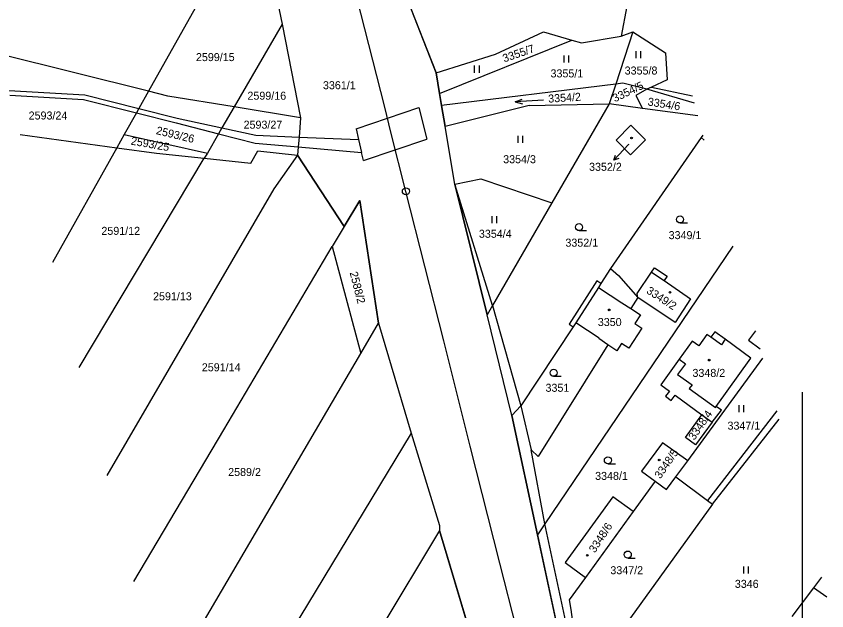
# Model space of a CAD drawing. Extents: x -754710 to -754206, y -1169123 to -1168234.
# Drawn here: x -754541.8 to -754369.7, y -1168754.2 to -1168628 of the extents above; entities that cross this region are included whole.
import ezdxf

# ---------------------------------------------------------------- set-up
doc = ezdxf.new("R2010")
doc.units = 0
for name, color, linetype in [('Vrstva 1', 7, 'Continuous'), ('Vrstva 16', 7, 'Continuous'), ('Vrstva 18', 7, 'Continuous'), ('Vrstva 19', 7, 'Continuous'), ('Vrstva 25', 7, 'Continuous'), ('Vrstva 3', 7, 'Continuous'), ('Vrstva 4', 7, 'Continuous'), ('Vrstva 6', 7, 'Continuous')]:
    doc.layers.add(name, color=color, linetype=linetype)

msp = doc.modelspace()

# ---------------------------------------------------------------- linework, layer by layer
at = {"layer": 'Vrstva 1'}
for p, q in [((-754463.59, -1168647.3), (-754471.68, -1168615.35)), ((-754460.6, -1168619.67), (-754452.67, -1168639.96)), ((-754486.32, -1168624.94), (-754485.38, -1168629.68)), ((-754412.19, -1168625.83), (-754413.36, -1168632.2)), ((-754485.38, -1168629.68), (-754481.43, -1168649.55)), ((-754440.06, -1168636.05), (-754429.88, -1168631.27)), ((-754429.88, -1168631.27), (-754423.86, -1168633.01)), ((-754421.81, -1168633.6), (-754413.36, -1168632.2)), ((-754413.36, -1168632.2), (-754410.89, -1168631.27)), ((-754410.89, -1168631.27), (-754404, -1168635.7)), ((-754423.86, -1168633.01), (-754421.81, -1168633.6)), ((-754513.7, -1168643.9), (-754545.33, -1168636.05)), ((-754452.67, -1168639.96), (-754440.06, -1168636.05)), ((-754404, -1168635.7), (-754403.6, -1168641.5)), ((-754452.67, -1168639.96), (-754451.93, -1168644.34)), ((-754414.55, -1168642.38), (-754451.5, -1168646.92)), ((-754413.07, -1168642.2), (-754414.55, -1168642.38)), ((-754407.94, -1168643.48), (-754413.07, -1168642.2)), ((-754406.98, -1168643.04), (-754407.94, -1168643.48)), ((-754403.6, -1168641.5), (-754406.98, -1168643.04)), ((-754406.98, -1168643.04), (-754398.28, -1168644.85)), ((-754509.58, -1168644.92), (-754513.7, -1168643.9)), ((-754495.56, -1168647.23), (-754509.58, -1168644.92)), ((-754451.93, -1168644.34), (-754451.5, -1168646.92)), ((-754432.9, -1168646.9), (-754415.92, -1168646.53)), ((-754415.92, -1168646.53), (-754428.1, -1168667.57)), ((-754408.83, -1168647.52), (-754415.92, -1168646.53)), ((-754481.43, -1168649.55), (-754495.56, -1168647.23)), ((-754462.25, -1168652.61), (-754463.59, -1168647.3)), ((-754451.5, -1168646.92), (-754450.74, -1168651.41)), ((-754432.9, -1168646.9), (-754450.74, -1168651.41)), ((-754397.13, -1168649.14), (-754408.83, -1168647.52)), ((-754481.43, -1168649.55), (-754481.76, -1168653.61)), ((-754448.68, -1168663.63), (-754450.74, -1168651.41)), ((-754411.33, -1168651.11), (-754414.47, -1168654.27)), ((-754408.23, -1168654.21), (-754411.33, -1168651.11)), ((-754540.99, -1168653.08), (-754520.42, -1168655.89)), ((-754459.07, -1168665.21), (-754462.25, -1168652.61)), ((-754396.05, -1168653.18), (-754396.4, -1168653.69)), ((-754481.76, -1168653.61), (-754481.94, -1168655.69)), ((-754396.4, -1168653.69), (-754415.64, -1168681.53)), ((-754414.47, -1168654.27), (-754411.38, -1168657.36)), ((-754411.38, -1168657.36), (-754408.23, -1168654.21)), ((-754396.4, -1168653.69), (-754395.75, -1168654.27)), ((-754520.42, -1168655.89), (-754512.05, -1168657.04)), ((-754492.02, -1168659.16), (-754490.52, -1168656.57)), ((-754490.52, -1168656.57), (-754482.08, -1168657.45)), ((-754481.94, -1168655.69), (-754482.08, -1168657.45)), ((-754512.05, -1168657.04), (-754501.88, -1168658.12)), ((-754501.88, -1168658.12), (-754492.02, -1168659.16)), ((-754472.22, -1168672.58), (-754482.08, -1168657.45)), ((-754448.68, -1168663.63), (-754441.87, -1168691.36)), ((-754451.06, -1168696.87), (-754459.07, -1168665.21)), ((-754468.86, -1168667.12), (-754472.22, -1168672.58)), ((-754464.89, -1168693.12), (-754468.86, -1168667.12)), ((-754428.1, -1168667.57), (-754440.72, -1168689.36)), ((-754472.22, -1168672.58), (-754474.73, -1168676.83)), ((-754497.71, -1168715.77), (-754474.73, -1168676.83)), ((-754474.73, -1168676.83), (-754468.68, -1168699.59)), ((-754389.72, -1168676.8), (-754429.57, -1168735.76)), ((-754415.64, -1168681.53), (-754417.68, -1168684.71)), ((-754415.64, -1168681.53), (-754413.94, -1168682.99)), ((-754410.01, -1168686.86), (-754406.97, -1168682.3)), ((-754406.97, -1168682.3), (-754406.35, -1168681.37)), ((-754406.35, -1168681.37), (-754403.66, -1168683.16)), ((-754418.53, -1168684.17), (-754424.41, -1168693.34)), ((-754417.68, -1168684.71), (-754418.53, -1168684.17)), ((-754413.94, -1168682.99), (-754409.88, -1168687.67)), ((-754403.66, -1168683.16), (-754404.29, -1168684.1)), ((-754404.29, -1168684.1), (-754398.67, -1168687.96)), ((-754409.88, -1168687.67), (-754411.36, -1168690.04)), ((-754409.88, -1168687.67), (-754410.01, -1168686.86)), ((-754401.94, -1168693.01), (-754409.88, -1168687.67)), ((-754440.72, -1168689.36), (-754441.87, -1168691.36)), ((-754398.67, -1168687.96), (-754401.94, -1168693.01)), ((-754436.63, -1168712.73), (-754441.87, -1168691.36)), ((-754411.36, -1168690.04), (-754409.3, -1168691.38)), ((-754409.3, -1168691.38), (-754410.48, -1168693.2)), ((-754423.03, -1168693.04), (-754423.57, -1168693.88)), ((-754418.08, -1168696.32), (-754423.03, -1168693.04)), ((-754468.68, -1168699.59), (-754464.89, -1168693.12)), ((-754464.89, -1168693.12), (-754457.95, -1168716.5)), ((-754423.57, -1168693.88), (-754434.7, -1168710.71)), ((-754424.41, -1168693.34), (-754423.57, -1168693.88)), ((-754408.98, -1168694.18), (-754411.76, -1168698.45)), ((-754410.48, -1168693.2), (-754408.98, -1168694.18)), ((-754384.9, -1168694.76), (-754386.35, -1168696.77)), ((-754418.1, -1168696.41), (-754418.08, -1168696.32)), ((-754416.19, -1168697.75), (-754418.1, -1168696.41)), ((-754395.18, -1168695.53), (-754396.93, -1168697.95)), ((-754394.33, -1168696.13), (-754395.18, -1168695.53)), ((-754393.52, -1168694.99), (-754394.33, -1168696.13)), ((-754391.34, -1168696.54), (-754393.52, -1168694.99)), ((-754385.86, -1168700.53), (-754391.34, -1168696.54)), ((-754445.42, -1168719.24), (-754451.06, -1168696.87)), ((-754416.19, -1168697.75), (-754431.01, -1168721.45)), ((-754414.34, -1168699.04), (-754416.19, -1168697.75)), ((-754413.3, -1168697.45), (-754414.34, -1168699.04)), ((-754411.76, -1168698.45), (-754413.3, -1168697.45)), ((-754398.33, -1168696.96), (-754401.06, -1168700.75)), ((-754396.93, -1168697.95), (-754398.33, -1168696.96)), ((-754386.35, -1168696.77), (-754383.88, -1168698.57)), ((-754510.83, -1168771.56), (-754468.68, -1168699.59)), ((-754401.06, -1168700.75), (-754404.95, -1168706.25)), ((-754399.26, -1168722.38), (-754383.35, -1168700.57)), ((-754393.21, -1168710.84), (-754385.86, -1168700.53)), ((-754404.95, -1168706.25), (-754403.16, -1168707.56)), ((-754403.16, -1168707.56), (-754403.96, -1168708.65)), ((-754402.75, -1168709.54), (-754401.95, -1168708.44)), ((-754401.95, -1168708.44), (-754396.29, -1168712.57)), ((-754403.96, -1168708.65), (-754402.75, -1168709.54)), ((-754434.7, -1168710.71), (-754436.63, -1168712.73)), ((-754434.7, -1168710.71), (-754432.51, -1168719.99)), ((-754380.36, -1168711.71), (-754395.05, -1168730.8)), ((-754394.09, -1168714.17), (-754392.08, -1168711.61)), ((-754392.08, -1168711.61), (-754393.21, -1168710.84)), ((-754436.63, -1168712.73), (-754431.15, -1168738.1)), ((-754399.77, -1168717.39), (-754396.29, -1168712.57)), ((-754396.29, -1168712.57), (-754394.09, -1168714.17)), ((-754394.09, -1168714.17), (-754397.64, -1168718.98)), ((-754516.83, -1168748.01), (-754497.71, -1168715.77)), ((-754457.95, -1168716.5), (-754505.08, -1168794.17)), ((-754457.95, -1168716.5), (-754451.94, -1168736.1)), ((-754404.62, -1168718.51), (-754409.11, -1168724.52)), ((-754399.26, -1168722.38), (-754404.62, -1168718.51)), ((-754397.64, -1168718.98), (-754399.77, -1168717.39)), ((-754439.13, -1168744.08), (-754445.42, -1168719.24)), ((-754431.01, -1168721.45), (-754432.51, -1168719.99)), ((-754401.8, -1168725.79), (-754399.26, -1168722.38)), ((-754409.11, -1168724.52), (-754406.17, -1168726.67)), ((-754403.75, -1168728.44), (-754401.8, -1168725.79)), ((-754401.8, -1168725.79), (-754395.05, -1168730.8)), ((-754406.17, -1168726.67), (-754410.83, -1168733.1)), ((-754406.17, -1168726.67), (-754403.75, -1168728.44)), ((-754415.14, -1168729.97), (-754425.29, -1168743.98)), ((-754410.83, -1168733.1), (-754415.14, -1168729.97)), ((-754395.05, -1168730.8), (-754394.02, -1168731.56)), ((-754394.02, -1168731.56), (-754421.18, -1168769.2)), ((-754410.83, -1168733.1), (-754420.98, -1168747.1)), ((-754451.94, -1168736.1), (-754451.95, -1168737.18)), ((-754451.95, -1168737.18), (-754499.53, -1168815.95)), ((-754445.36, -1168759.13), (-754451.95, -1168737.18)), ((-754431.15, -1168738.1), (-754426.48, -1168759.73)), ((-754434.25, -1168763.41), (-754439.13, -1168744.08)), ((-754425.29, -1168743.98), (-754420.98, -1168747.1)), ((-754420.98, -1168747.1), (-754424.45, -1168751.89)), ((-754370.88, -1168747.09), (-754372.58, -1168749.34)), ((-754372.58, -1168749.34), (-754377.16, -1168755.42)), ((-754369.75, -1168751.32), (-754372.58, -1168749.34)), ((-754424.45, -1168751.89), (-754424.07, -1168753.9)), ((-754424.07, -1168753.9), (-754423.79, -1168756.05))]:
    msp.add_line(p, q, dxfattribs=at)
for points in [[(-754378.16, -1168960.13), (-754379.05, -1168945.33), (-754396.56, -1168868.29), (-754401.41, -1168844.82), (-754410.22, -1168837.85), (-754411.61, -1168830.11), (-754417.05, -1168810.66), (-754423.83, -1168771.88), (-754425.2, -1168765.6), (-754426.48, -1168759.73), (-754431.15, -1168738.1), (-754436.63, -1168712.73), (-754441.87, -1168691.36), (-754448.68, -1168663.63), (-754450.74, -1168651.41), (-754451.5, -1168646.92), (-754451.93, -1168644.34), (-754452.67, -1168639.96), (-754460.6, -1168619.67)], [(-754486.32, -1168624.94), (-754485.38, -1168629.68), (-754481.43, -1168649.55), (-754481.76, -1168653.61), (-754481.94, -1168655.69), (-754482.08, -1168657.45), (-754472.22, -1168672.58), (-754468.86, -1168667.12), (-754464.89, -1168693.12), (-754457.95, -1168716.5), (-754451.94, -1168736.1), (-754451.95, -1168737.18), (-754445.36, -1168759.13)]]:
    msp.add_lwpolyline(points, dxfattribs=at)
msp.add_circle((-754459.08, -1168665.13), 0.75, dxfattribs=at)
at = {"layer": 'Vrstva 16'}
for p in [(-754411.74, -1168655.16), (-754414.94, -1168658.54)]:
    msp.add_line(p, (-754412.88, -1168656.36), dxfattribs=at)
msp.add_lwpolyline([(-754413.89, -1168658.16), (-754414.94, -1168658.54), (-754414.62, -1168657.47)], dxfattribs=at)
at = {"layer": 'Vrstva 25'}
for p, q in [((-754425.48, -1168637.81), (-754425.48, -1168636.31)), ((-754424.48, -1168637.81), (-754424.48, -1168636.31)), ((-754410.2, -1168636.9), (-754410.2, -1168635.4)), ((-754409.2, -1168636.9), (-754409.2, -1168635.4)), ((-754444.49, -1168639.95), (-754444.49, -1168638.45)), ((-754443.49, -1168639.95), (-754443.49, -1168638.45)), ((-754435.23, -1168654.85), (-754435.23, -1168653.35)), ((-754434.23, -1168654.85), (-754434.23, -1168653.35)), ((-754440.76, -1168671.92), (-754440.76, -1168670.42)), ((-754439.76, -1168671.92), (-754439.76, -1168670.42)), ((-754400.89, -1168671.86), (-754399.29, -1168671.86)), ((-754422.33, -1168673.49), (-754420.73, -1168673.49)), ((-754427.73, -1168704.41), (-754426.13, -1168704.41)), ((-754388.33, -1168712.05), (-754388.33, -1168710.55)), ((-754387.33, -1168712.05), (-754387.33, -1168710.55)), ((-754416.21, -1168722.99), (-754414.61, -1168722.99)), ((-754411.99, -1168743.01), (-754410.39, -1168743.01)), ((-754387.34, -1168746.31), (-754387.34, -1168744.81)), ((-754386.34, -1168746.31), (-754386.34, -1168744.81))]:
    msp.add_line(p, q, dxfattribs=at)
for points in [[(-754435.89, -1168646.14), (-754434.42, -1168645.55)], [(-754429.9, -1168645.8), (-754435.89, -1168646.14), (-754434.36, -1168646.55)]]:
    msp.add_lwpolyline(points, dxfattribs=at)
for centre, radius in [((-754411.19, -1168653.81), 0.175), ((-754400.89, -1168671.11), 0.75), ((-754422.33, -1168672.74), 0.75), ((-754403.03, -1168686.58), 0.175), ((-754415.93, -1168690.31), 0.175), ((-754394.71, -1168700.98), 0.175), ((-754427.73, -1168703.66), 0.75), ((-754416.21, -1168722.24), 0.75), ((-754405.31, -1168722.17), 0.175), ((-754420.59, -1168742.41), 0.175), ((-754411.99, -1168742.26), 0.75)]:
    msp.add_circle(centre, radius, dxfattribs=at)
at = {"layer": 'Vrstva 3'}
msp.add_lwpolyline([(-754375, -1168707.79), (-754375, -1169000), (-754517.39, -1169000)], dxfattribs=at)
at = {"layer": 'Vrstva 4'}
for p, q in [((-754543.38, -1168643.7), (-754527.26, -1168644.67)), ((-754543.12, -1168644.71), (-754527.5, -1168645.65)), ((-754527.26, -1168644.67), (-754515.75, -1168647.56)), ((-754527.5, -1168645.65), (-754516.26, -1168648.47)), ((-754515.75, -1168647.56), (-754507.64, -1168649.6)), ((-754469.63, -1168651.87), (-754456.36, -1168647.37)), ((-754456.36, -1168647.37), (-754454.61, -1168654.08)), ((-754516.26, -1168648.47), (-754507.88, -1168650.57)), ((-754507.64, -1168649.6), (-754498.13, -1168651.66)), ((-754507.88, -1168650.57), (-754498.85, -1168652.9)), ((-754498.13, -1168651.66), (-754490.96, -1168653.21)), ((-754498.85, -1168652.9), (-754491.11, -1168654.89)), ((-754490.96, -1168653.21), (-754481.76, -1168653.61)), ((-754469.63, -1168651.87), (-754469.11, -1168654.15)), ((-754491.11, -1168654.89), (-754481.94, -1168655.69)), ((-754481.76, -1168653.61), (-754469.11, -1168654.15)), ((-754469.11, -1168654.15), (-754468.49, -1168656.87)), ((-754468.1, -1168658.6), (-754454.61, -1168654.08)), ((-754481.94, -1168655.69), (-754468.49, -1168656.87)), ((-754468.1, -1168658.6), (-754468.49, -1168656.87)), ((-754440.72, -1168689.36), (-754448.68, -1168663.63)), ((-754406.97, -1168682.3), (-754404.29, -1168684.1)), ((-754418.22, -1168685.55), (-754423.03, -1168693.04)), ((-754417.68, -1168684.71), (-754418.22, -1168685.55)), ((-754418.22, -1168685.55), (-754413.25, -1168688.81)), ((-754440.72, -1168689.36), (-754434.7, -1168710.71)), ((-754413.25, -1168688.81), (-754411.36, -1168690.04)), ((-754392.13, -1168697.71), (-754394.33, -1168696.13)), ((-754391.34, -1168696.54), (-754392.13, -1168697.71)), ((-754401.06, -1168700.75), (-754399.72, -1168701.74)), ((-754399.72, -1168701.74), (-754401.46, -1168704.02)), ((-754401.46, -1168704.02), (-754398.34, -1168706.25)), ((-754398.34, -1168706.25), (-754398.97, -1168706.99)), ((-754398.97, -1168706.99), (-754393.36, -1168711.05)), ((-754393.36, -1168711.05), (-754393.21, -1168710.84)), ((-754394.02, -1168731.56), (-754379.88, -1168713.51)), ((-754429.57, -1168735.76), (-754432.51, -1168719.99)), ((-754424.91, -1168757.57), (-754429.57, -1168735.76))]:
    msp.add_line(p, q, dxfattribs=at)
at = {"layer": 'Vrstva 6'}
for p, q in [((-754499.81, -1168619.14), (-754513.7, -1168643.9)), ((-754485.38, -1168629.68), (-754495.56, -1168647.23)), ((-754410.89, -1168631.27), (-754414.55, -1168642.38)), ((-754451.93, -1168644.34), (-754423.86, -1168633.01)), ((-754414.55, -1168642.38), (-754415.92, -1168646.53)), ((-754513.7, -1168643.9), (-754515.75, -1168647.56)), ((-754407.94, -1168643.48), (-754410.28, -1168644.8)), ((-754410.28, -1168644.8), (-754408.83, -1168647.52)), ((-754397.86, -1168646.39), (-754407.94, -1168643.48)), ((-754515.75, -1168647.56), (-754516.26, -1168648.47)), ((-754495.56, -1168647.23), (-754498.13, -1168651.66)), ((-754516.26, -1168648.47), (-754518.85, -1168653.1)), ((-754498.13, -1168651.66), (-754498.85, -1168652.9)), ((-754518.85, -1168653.1), (-754520.42, -1168655.89)), ((-754518.85, -1168653.1), (-754501.23, -1168657.01)), ((-754498.85, -1168652.9), (-754501.23, -1168657.01)), ((-754520.42, -1168655.89), (-754534.08, -1168680.23)), ((-754528.41, -1168702.51), (-754501.88, -1168658.12)), ((-754501.23, -1168657.01), (-754501.88, -1168658.12)), ((-754482.08, -1168657.45), (-754487.11, -1168664.61)), ((-754448.68, -1168663.63), (-754443.21, -1168662.48)), ((-754443.21, -1168662.48), (-754428.1, -1168667.57)), ((-754487.11, -1168664.61), (-754522.56, -1168725.47)), ((-754429.57, -1168735.76), (-754431.15, -1168738.1))]:
    msp.add_line(p, q, dxfattribs=at)

# ---------------------------------------------------------------- texts
at = {"layer": 'Vrstva 16'}
msp.add_text('3352/2', height=1.7, dxfattribs=at).set_placement((-754420.21, -1168660.78))
at = {"layer": 'Vrstva 18'}
for s, rotation, p in [('3355/7', 18.9076, (-754438.21, -1168637.78)), ('3354/5', 25.4966, (-754414.73, -1168646.25)), ('3354/2', 3.6096, (-754428.83, -1168646.32)), ('3354/6', 350.9939, (-754407.85, -1168646.89)), ('2593/26', 346.5249, (-754512.22, -1168652.97)), ('2593/25', 350.0772, (-754517.56, -1168655.21)), ('2588/2', 284.4162, (-754471.03, -1168682.42)), ('3348/4', 55.5196, (-754397.87, -1168718.11))]:
    msp.add_text(s, height=1.7, rotation=rotation, dxfattribs=at).set_placement(p)
for s, p in [('2599/15', (-754503.65, -1168637.49)), ('3355/1', (-754428.39, -1168640.95)), ('3355/8', (-754412.65, -1168640.34)), ('3361/1', (-754476.69, -1168643.46)), ('2599/16', (-754492.72, -1168645.69)), ('2593/24', (-754539.16, -1168649.89)), ('2593/27', (-754493.54, -1168651.84)), ('3354/3', (-754438.44, -1168659.17)), ('2591/12', (-754523.72, -1168674.38)), ('3354/4', (-754443.59, -1168675)), ('3349/1', (-754403.32, -1168675.29)), ('3352/1', (-754425.23, -1168676.89)), ('2591/13', (-754512.75, -1168688.27)), ('2591/14', (-754502.4, -1168703.35)), ('3351', (-754429.45, -1168707.7)), ('3347/1', (-754390.82, -1168715.74)), ('2589/2', (-754496.81, -1168725.58)), ('3348/1', (-754418.92, -1168726.41)), ('3347/2', (-754415.69, -1168746.44)), ('3346', (-754389.27, -1168749.33))]:
    msp.add_text(s, height=1.7, dxfattribs=at).set_placement(p)
at = {"layer": 'Vrstva 19'}
for s, height, p in [('3352/2', 0.1, (-754412, -1168655.16)), ('3350', 1.7, (-754418.35, -1168693.74)), ('3348/2', 1.7, (-754398.26, -1168704.54))]:
    msp.add_text(s, height=height, dxfattribs=at).set_placement(p)
for s, rotation, p in [('3349/2', 327.1016, (-754408.18, -1168686.65)), ('3348/5', 55.405, (-754405.08, -1168726.31)), ('3348/6', 56.7228, (-754418.97, -1168742.02))]:
    msp.add_text(s, height=1.7, rotation=rotation, dxfattribs=at).set_placement(p)

doc.saveas('drawing.dxf')
